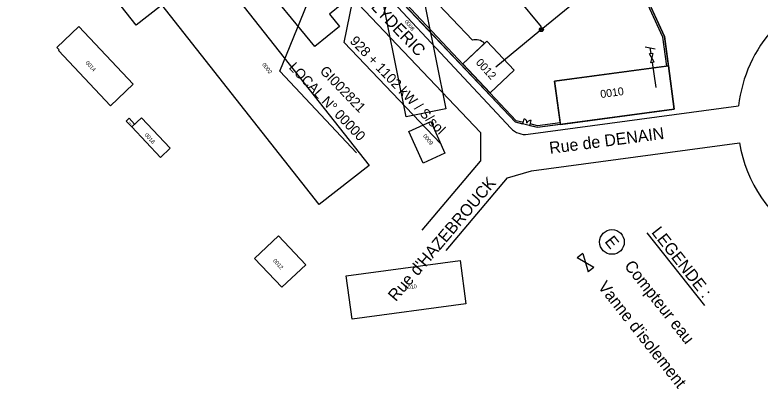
# Model space of a CAD drawing. Extents: x 703432 to 707394, y 7057985 to 7059523.
# Drawn here: x 704711.1 to 704899.3, y 7059167.2 to 7059261.6 of the extents above; entities that cross this region are included whole.
import ezdxf

# ---------------------------------------------------------------- set-up
doc = ezdxf.new("R2010")
doc.units = 0
for name, color, linetype in [('DH_HACHURE-MOTIF', 7, 'Continuous'), ('DH_TEXTE', 7, 'Continuous'), ('GEOSID_BATI_AERIEN _POLYGONE', 7, 'Continuous'), ('GEOSID_BATI_AERIEN_NUMERO', 7, 'Continuous'), ('GO_MUR_EXTERIEUR', 7, 'Continuous'), ('IMM_LIMITE PHYSIQUE', 7, 'Continuous'), ('LIB_08', 7, 'Continuous'), ('RES_EAU BASSE PRESSION', 7, 'Continuous'), ('RES_EAU BASSE PRESSION - EQUIP - TEXTE', 7, 'Continuous'), ('SID_NUMERO_BATI', 7, 'Continuous'), ('SID_POLYLIGNES_BATI', 7, 'Continuous'), ('SID_POLYLIGNES_IMMEUBLE', 7, 'Continuous'), ('VOIRIE_BORDURE', 7, 'Continuous'), ('VOIRIE_ROUTE', 7, 'Continuous')]:
    doc.layers.add(name, color=color, linetype=linetype)

msp = doc.modelspace()

# ---------------------------------------------------------------- linework, layer by layer
at = {"layer": 'DH_HACHURE-MOTIF'}
for points in [[(704829.75, 7059254.38), (704824.29, 7059249.23), (704831.15, 7059241.95), (704837.19, 7059247.66), (704830.33, 7059254.93), (704829.75, 7059254.38)], [(704848.84, 7059234.37), (704848.9, 7059233.93), (704877.64, 7059237.78), (704876.18, 7059248.69), (704875.73, 7059248.63), (704847.43, 7059244.83), (704848.84, 7059234.37)]]:
    msp.add_lwpolyline(points, dxfattribs=at)
at = {"layer": 'GEOSID_BATI_AERIEN _POLYGONE'}
for points in [[(704711.1, 7059297.85), (704724.14, 7059308.13), (704754.79, 7059269.27), (704741.76, 7059258.99)], [(704772.33, 7059271.39), (704778.52, 7059276.46), (704781.05, 7059273.37), (704784.15, 7059275.9), (704793.66, 7059264.3), (704790.56, 7059261.77), (704793.1, 7059258.67), (704786.91, 7059253.6)], [(704748.24, 7059264.09), (704754.8, 7059269.27), (704754.18, 7059270.06), (704760.18, 7059274.79), (704800.56, 7059223.61), (704788, 7059213.7)], [(704802.58, 7059272.25), (704812.6, 7059274.26), (704819.92, 7059237.89), (704809.91, 7059235.87)], [(704721.73, 7059253.37), (704727.28, 7059258.61), (704741.01, 7059244.06), (704735.29, 7059238.66), (704722.15, 7059252.59), (704722.31, 7059252.75)], [(704739.21, 7059234.8), (704739.93, 7059235.49), (704741.35, 7059233.98), (704740.63, 7059233.29)], [(704740.63, 7059233.29), (704743.08, 7059235.6), (704750.32, 7059227.93), (704747.87, 7059225.62)], [(704810.61, 7059232.16), (704816.14, 7059234.66), (704819.75, 7059226.67), (704814.22, 7059224.17)], [(704771.66, 7059200.11), (704777.7, 7059205.82), (704784.57, 7059198.54), (704778.52, 7059192.84)], [(704796.27, 7059184.81), (704794.8, 7059195.72), (704823.55, 7059199.57), (704825.01, 7059188.67)]]:
    msp.add_lwpolyline(points, close=True, dxfattribs=at)
at = {"layer": 'GO_MUR_EXTERIEUR'}
for p, q in [((704824.29, 7059249.23), (704830.33, 7059254.93)), ((704830.33, 7059254.93), (704837.19, 7059247.66)), ((704831.15, 7059241.95), (704824.29, 7059249.23)), ((704847.43, 7059244.83), (704876.18, 7059248.69)), ((704876.18, 7059248.69), (704877.64, 7059237.78)), ((704837.19, 7059247.66), (704831.15, 7059241.95)), ((704848.9, 7059233.93), (704847.43, 7059244.83)), ((704877.64, 7059237.78), (704848.9, 7059233.93))]:
    msp.add_line(p, q, dxfattribs=at)
at = {"layer": 'IMM_LIMITE PHYSIQUE'}
for p, q in [((704773.82, 7059301.99), (704837.52, 7059234.47)), ((704774.15, 7059302.3), (704837.75, 7059234.88)), ((704839.45, 7059234.02), (704837.52, 7059234.47)), ((704839.55, 7059234.46), (704837.75, 7059234.88)), ((704839.45, 7059234.02), (704839.75, 7059235.31)), ((704841.2, 7059233.61), (704841.5, 7059234.9)), ((704843.13, 7059233.15), (704841.2, 7059233.61)), ((704843.15, 7059233.61), (704841.3, 7059234.05)), ((704848.9, 7059233.93), (704843.13, 7059233.15)), ((704848.84, 7059234.37), (704843.15, 7059233.61))]:
    msp.add_line(p, q, dxfattribs=at)
for points in [[(704875.79, 7059248.63), (704874.76, 7059255.98), (704866.86, 7059273.26)], [(704876.24, 7059248.69), (704875.2, 7059256.1), (704867.27, 7059273.44)]]:
    msp.add_lwpolyline(points, dxfattribs=at)
for centre, start, end in [((704839.58, 7059234.45), 346.7916, 78.7098), ((704841.28, 7059234.05), 75.2683, 166.7916)]:
    msp.add_arc(centre, 0.874, start, end, dxfattribs=at)
at = {"layer": 'LIB_08'}
for points in [[(704818.61, 7059229.1), (704794.32, 7059254.63), (704805.74, 7059310.57)], [(704797.43, 7059226.8), (704778.01, 7059247.38), (704793.84, 7059286.23)]]:
    msp.add_lwpolyline(points, dxfattribs=at)
at = {"layer": 'RES_EAU BASSE PRESSION'}
for p, q in [((704867.34, 7059276.91), (704844.48, 7059258.18)), ((704829.13, 7059276.6), (704844.03, 7059258.56)), ((704843.67, 7059257.52), (704832.55, 7059248.4)), ((704870.34, 7059253.56), (704872.87, 7059253.03)), ((704871.81, 7059251.81), (704871.6, 7059253.29)), ((704872.26, 7059251.87), (704871.37, 7059251.75)), ((704872.57, 7059249.64), (704871.37, 7059251.75)), ((704872.26, 7059251.87), (704871.68, 7059249.52)), ((704872.57, 7059249.64), (704871.68, 7059249.52)), ((704872.12, 7059249.58), (704873.01, 7059243.28))]:
    msp.add_line(p, q, dxfattribs=at)
at = {"layer": 'RES_EAU BASSE PRESSION - EQUIP - TEXTE'}
for p, q in [((704870.76, 7059206.61), (704885.27, 7059188.22)), ((704854.57, 7059201.35), (704853.16, 7059200.24)), ((704857.36, 7059197.82), (704853.16, 7059200.24)), ((704854.57, 7059201.35), (704855.95, 7059196.7)), ((704857.36, 7059197.82), (704855.95, 7059196.7))]:
    msp.add_line(p, q, dxfattribs=at)
for centre, radius in [((704844.1, 7059257.87), 0.5), ((704844.1, 7059257.87), 0.45), ((704844.1, 7059257.87), 0.25), ((704844.1, 7059257.87), 0.05), ((704861.92, 7059204.28), 3.12)]:
    msp.add_circle(centre, radius, dxfattribs=at)
at = {"layer": 'SID_POLYLIGNES_BATI'}
for p, q in [((704824.29, 7059249.23), (704830.33, 7059254.93)), ((704830.33, 7059254.93), (704837.19, 7059247.66)), ((704831.15, 7059241.95), (704824.29, 7059249.23)), ((704847.43, 7059244.83), (704876.18, 7059248.69)), ((704876.18, 7059248.69), (704877.64, 7059237.78)), ((704837.19, 7059247.66), (704831.15, 7059241.95)), ((704848.9, 7059233.93), (704847.43, 7059244.83)), ((704877.64, 7059237.78), (704848.9, 7059233.93))]:
    msp.add_line(p, q, dxfattribs=at)
at = {"layer": 'SID_POLYLIGNES_IMMEUBLE'}
for p, q in [((704837.52, 7059234.47), (704748.31, 7059329.03)), ((704867.27, 7059273.44), (704875.2, 7059256.1)), ((704875.2, 7059256.1), (704877.64, 7059237.78))]:
    msp.add_line(p, q, dxfattribs=at)
msp.add_lwpolyline([(704877.64, 7059237.78), (704843.13, 7059233.15), (704837.52, 7059234.47)], dxfattribs=at)
at = {"layer": 'VOIRIE_BORDURE'}
msp.add_line((704816.39, 7059266.07), (704826.66, 7059255.18), dxfattribs=at)
msp.add_arc((704827.57, 7059252.32), 3, 43.3308, 107.6513, dxfattribs=at)
at = {"layer": 'VOIRIE_ROUTE'}
for p, q in [((704828.72, 7059231.87), (704772.01, 7059291.53)), ((704784.08, 7059289.06), (704836.4, 7059232.99)), ((704828.72, 7059231.87), (704828.69, 7059224.65)), ((704813.95, 7059207.27), (704828.69, 7059224.65))]:
    msp.add_line(p, q, dxfattribs=at)
for points in [[(704840.72, 7059231.44), (704893.92, 7059238.59)], [(704820.03, 7059202.12), (704835.58, 7059220.47), (704841.64, 7059222.27), (704894.16, 7059229.33)]]:
    msp.add_lwpolyline(points, dxfattribs=at)
for centre, radius, start, end in [((704928.25, 7059234.85), 34.53, 137.2612, 173.7773), ((704840.06, 7059236.4), 5, 223.0213, 277.6524), ((704928.25, 7059234.85), 34.53, 189.1939, 289.1455)]:
    msp.add_arc(centre, radius, start, end, dxfattribs=at)

# ---------------------------------------------------------------- texts
at = {"layer": 'DH_TEXTE'}
for s, rotation, p in [('Rue LYDERIC', 313.8024, (704795.02, 7059269.55)), ('Rue de DENAIN', 7.4746, (704846.29, 7059226.5)), ("Rue d'HAZEBROUCK", 49.6268, (704807.35, 7059189.07))]:
    msp.add_text(s, height=3, rotation=rotation, dxfattribs=at).set_placement(p)
at = {"layer": 'GEOSID_BATI_AERIEN_NUMERO'}
for s, height, rotation, p in [('0008', 1, 309.3307, (704809.44, 7059259.85)), ('0014', 1, 312.5129, (704728.86, 7059249.43)), ('0002', 1, 308.2727, (704773.49, 7059249.01)), ('0013', 0.279, 312.5129, (704739.98, 7059234.5)), ('0018', 1, 312.5129, (704743.79, 7059231.22)), ('0009', 1, 309.3307, (704814.14, 7059231)), ('0012', 1, 312.5129, (704776.22, 7059199.48)), ('0010', 1, 8.0003, (704809.63, 7059192.23))]:
    msp.add_text(s, height=height, rotation=rotation, dxfattribs=at).set_placement(p)
at = {"layer": 'LIB_08'}
for s, p in [('928 + 1102 kW / S/sol', (704795.55, 7059254.81)), ('LOCAL N° 00000', (704780.15, 7059248.16)), ('GI002821', (704787.97, 7059247.26))]:
    msp.add_text(s, height=2.5, rotation=313.9654, dxfattribs=at).set_placement(p)
at = {"layer": 'RES_EAU BASSE PRESSION - EQUIP - TEXTE'}
for s, p in [('LEGENDE :', (704871.76, 7059206.68)), ('E', (704859.94, 7059204.36)), ('Compteur eau', (704864.89, 7059198.19)), ("Vanne d'isolement", (704858.24, 7059192.94))]:
    msp.add_text(s, height=3, rotation=308.2727, dxfattribs=at).set_placement(p)
at = {"layer": 'SID_NUMERO_BATI'}
for s, rotation, p in [('0012', 312.5129, (704827.4, 7059249.44)), ('0010', 8.0003, (704859.13, 7059240.57))]:
    msp.add_text(s, height=2, rotation=rotation, dxfattribs=at).set_placement(p)

doc.saveas('drawing.dxf')
